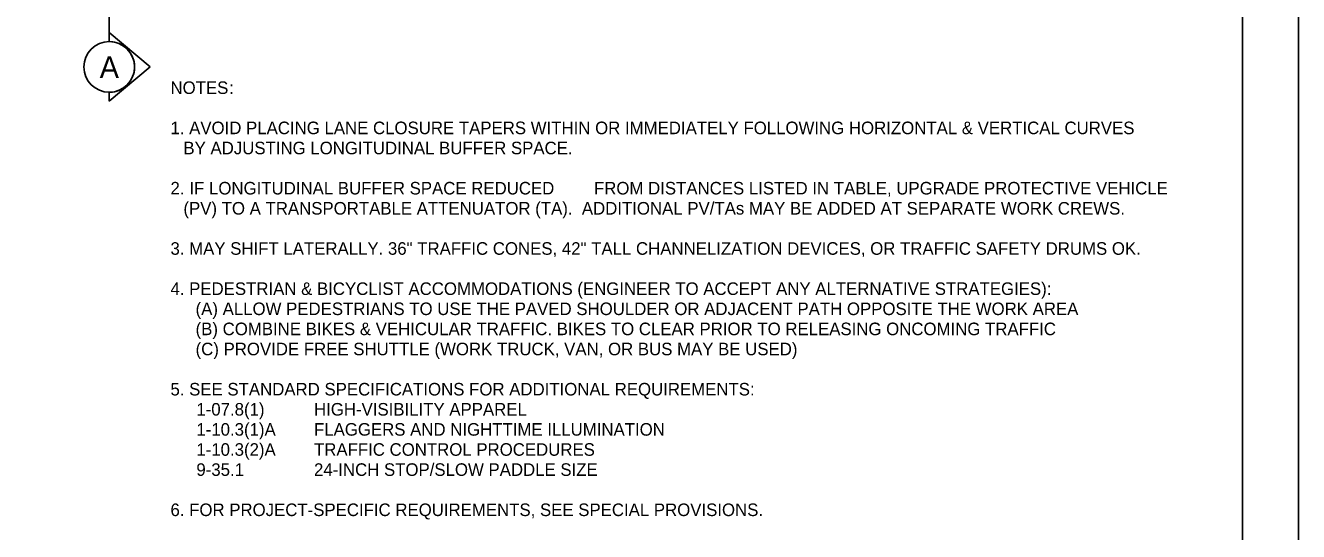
# Model space of a CAD drawing. Extents: x 99999.1 to 100095.7, y 99995 to 100010.7.
# Drawn here: x 100008.97 to 100016.06, y 100002.79 to 100005.61 of the extents above; entities that cross this region are included whole.
import ezdxf

# ---------------------------------------------------------------- set-up
doc = ezdxf.new("R2010")
doc.units = 0
for name, color, linetype in [('SH_GI_GeneralNotesBodyText', 7, 'Continuous'), ('SH_GI_PlotLimits', 7, 'Continuous'), ('SH_GI_SheetBorder', 7, 'Continuous'), ('SH_TI_WZSectionCut', 7, 'Continuous')]:
    doc.layers.add(name, color=color, linetype=linetype)

msp = doc.modelspace()

# ---------------------------------------------------------------- linework, layer by layer
at = {"layer": 'SH_GI_PlotLimits'}
msp.add_lwpolyline([(99999.0625, 99999.6875), (100016.0625, 99999.6875), (100016.0625, 100010.6875), (99999.0625, 100010.6875)], close=True, dxfattribs=at)
at = {"layer": 'SH_GI_SheetBorder'}
msp.add_line((100015.75, 100010.375), (100015.75, 100000), dxfattribs=at)
at = {"layer": 'SH_TI_WZSectionCut'}
for p, q in [((100009.4338, 100007.7022), (100009.4338, 100005.5723)), ((100009.4337, 100005.5723), (100009.4337, 100005.5224)), ((100009.6619, 100005.3812), (100009.4337, 100005.5723)), ((100009.4337, 100005.1901), (100009.6619, 100005.3812)), ((100009.4337, 100005.24), (100009.4337, 100005.1901))]:
    msp.add_line(p, q, dxfattribs=at)
msp.add_circle((100009.4338, 100005.3812), 0.1412, dxfattribs=at)
msp.add_arc((100009.4338, 100005.3812), 0.1412, 269.99779, 90.00221, dxfattribs=at)

# ---------------------------------------------------------------- texts
at = {"layer": 'SH_GI_GeneralNotesBodyText'}
for s, p in [('NOTES', (100009.7751, 100005.2306)), (':', (100010.1026, 100005.2306)), ('1. AVOID PLACING LANE CLOSURE TAPERS WITHIN OR IMMEDIATELY FOLLOWING HORIZONTAL & VERTICAL CURVES ', (100009.7751, 100005.0066)), ('BY ADJUSTING LONGITUDINAL BUFFER SPACE.', (100009.8473, 100004.8946)), ('2. ', (100009.7751, 100004.6706)), ('IF LONGITUDINAL BUFFER SPACE REDUCED', (100009.8808, 100004.6706)), (' FROM DISTANCES LISTED IN TABLE, UPGRADE PROTECTIVE VEHICLE ', (100012.1095, 100004.6706)), ('(PV) TO A TRANSPORTABLE ATTENUATOR (TA).  ADDITIONAL PV/TAs MAY BE ADDED AT SEPARATE WORK CREWS.', (100009.8473, 100004.5586)), ('3. MAY SHIFT LATERALLY. 36" TRAFFIC CONES, 42" TALL CHANNELIZATION DEVICES, OR TRAFFIC SAFETY DRUMS OK.', (100009.7751, 100004.3346)), ('4. PEDESTRIAN & BICYCLIST ACCOMMODATIONS (ENGINEER TO ACCEPT ANY ALTERNATIVE STRATEGIES):', (100009.7751, 100004.1106)), ('(A) ALLOW PEDESTRIANS TO USE THE PAVED SHOULDER OR ADJACENT PATH OPPOSITE THE WORK AREA', (100009.9151, 100003.9986)), ('(B) COMBINE BIKES & VEHICULAR TRAFFIC. BIKES TO CLEAR PRIOR TO RELEASING ONCOMING TRAFFIC', (100009.9151, 100003.8866)), ('(C) PROVIDE FREE SHUTTLE (WORK TRUCK, VAN, OR BUS MAY BE USED)', (100009.9151, 100003.7746)), ('5. SEE STANDARD SPECIFICATIONS FOR ADDITIONAL REQUIREMENTS:', (100009.7751, 100003.5506)), ('1-07.8(1) ', (100009.9195, 100003.4386)), ('HIGH-VISIBILITY APPAREL', (100010.5751, 100003.4386)), ('1-10.3(1)A ', (100009.9195, 100003.3266)), ('FLAGGERS AND NIGHTTIME ILLUMINATION', (100010.5751, 100003.3266)), ('1-10.3(2)A', (100009.9195, 100003.2146)), ('TRAFFIC CONTROL PROCEDURES', (100010.5751, 100003.2146)), ('9-35.1', (100009.9195, 100003.1026)), ('24-INCH STOP/SLOW PADDLE SIZE', (100010.5751, 100003.1026)), ('6. FOR PROJECT-SPECIFIC REQUIREMENTS, SEE SPECIAL PROVISIONS.', (100009.7751, 100002.8786))]:
    msp.add_text(s, height=0.07, rotation=360, dxfattribs=at).set_placement(p)
at = {"layer": 'SH_TI_WZSectionCut'}
msp.add_text('A', height=0.12, rotation=0.00995, dxfattribs=at).set_placement((100009.3808, 100005.3203))

doc.saveas('drawing.dxf')
